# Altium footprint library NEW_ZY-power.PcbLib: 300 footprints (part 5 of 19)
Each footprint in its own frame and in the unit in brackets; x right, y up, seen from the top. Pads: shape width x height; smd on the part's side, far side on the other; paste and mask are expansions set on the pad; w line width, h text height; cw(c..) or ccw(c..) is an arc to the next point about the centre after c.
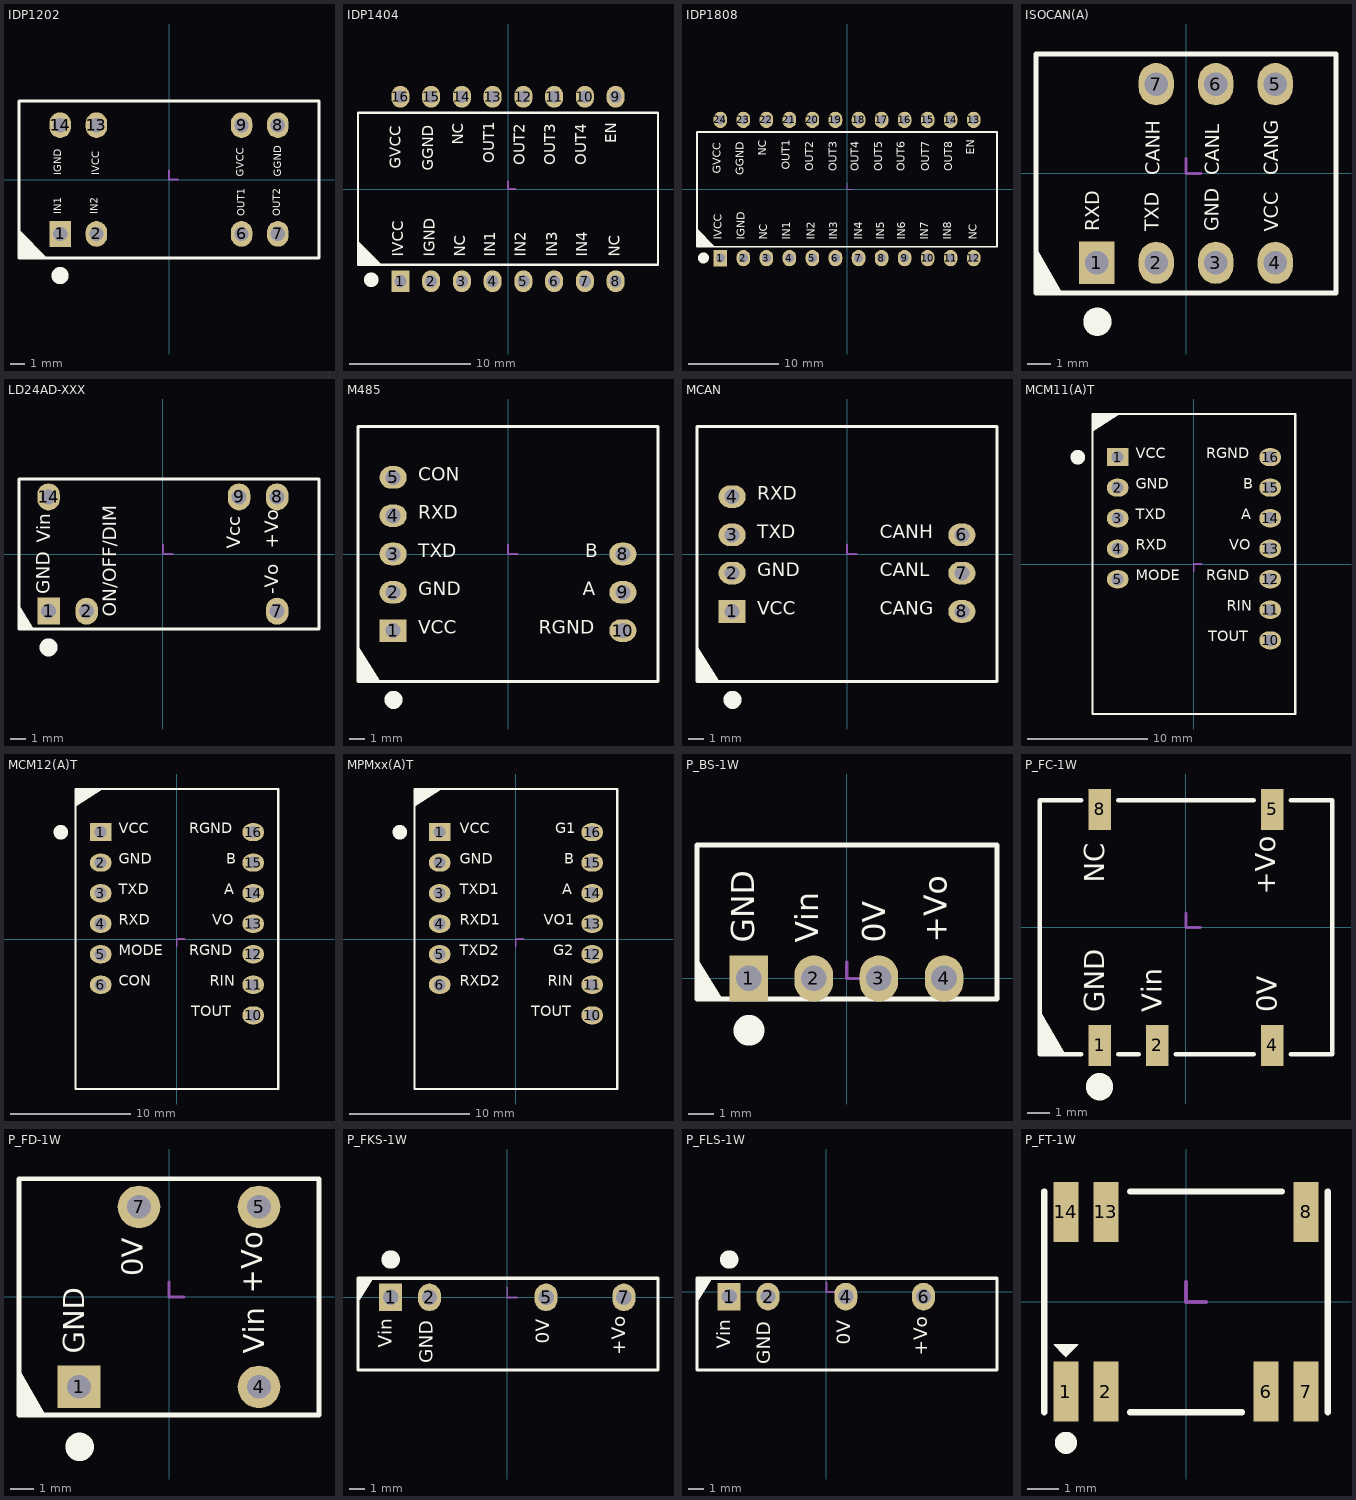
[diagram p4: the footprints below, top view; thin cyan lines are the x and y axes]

## IDP1202 [mm] "20x10x8mm"
height 8.001
pads (8):
  rect 1.5x1.8 hole 1: 1(-7.62,-3.81)
  oval 1.5x1.8 hole 1: 2(-5.08,-3.81) 6(5.08,-3.81) 7(7.62,-3.802) 8(7.62,3.81) 9(5.08,3.81) 13(-5.08,3.81) 14(-7.62,3.81)
Top Overlay:
  circle w1: c-7.62,-6.725 r0.1
  region: -10.5,-5.5 -8.525,-5.5 -10.5,-3.525
  lines w0.2: -10.5,-5.5 10.5,-5.5 10.5,5.5 -10.5,5.5 -10.5,-5.5
  text "IGND" at -7.366,0.305 h0.89
  text "IVCC" at -4.724,0.305 h0.89
  text "GVCC" at 5.41,0.178 h0.89
  text "GGND" at 8.026,0.178 h0.89
  text "OUT2" at 7.976,-2.565 h0.89
  text "OUT1" at 5.461,-2.565 h0.89
  text "IN1" at -7.366,-2.413 h0.89
  text "IN2" at -4.826,-2.413 h0.89
Mechanical 15:
  lines w0.127: 0,0.635 0,0 0.635,0

## IDP1404 [mm] "23.97x14.41x9.65mm"
height 9.652
pads (16):
  rect 1.5x1.8 hole 1: 1(-8.89,-7.62)
  oval 1.5x1.8 hole 1: 2(-6.35,-7.62) 3(-3.81,-7.62) 4(-1.27,-7.62) 5(1.27,-7.62) 6(3.81,-7.62) 7(6.35,-7.62) 8(8.89,-7.62) 9(8.89,7.62) 10(6.35,7.62) 11(3.81,7.62) 12(1.27,7.62) 13(-1.27,7.62) 14(-3.81,7.62) 15(-6.35,7.62) 16(-8.89,7.62)
Top Overlay:
  circle w1: c-11.303,-7.499 r0.1
  region: -12.39,-6.274 -10.415,-6.274 -12.39,-4.299
  lines w0.2: -12.39,-6.274 12.39,-6.274 12.39,6.299 -12.39,6.299 -12.39,-6.274
  text "IVCC" at -8.331,-5.588 h1.52
  text "IGND" at -5.74,-5.588 h1.52
  text "NC" at -3.2,-5.588 h1.52
  text "IN1" at -0.737,-5.588 h1.52
  text "IN2" at 1.778,-5.588 h1.52
  text "IN3" at 4.394,-5.588 h1.52
  text "IN4" at 6.883,-5.588 h1.52
  text "NC" at 9.576,-5.588 h1.52
  text "EN" at 9.271,3.791 h1.52
  text "OUT1" at -0.813,2.147 h1.52
  text "OUT2" at 1.702,1.968 h1.52
  text "OUT3" at 4.216,1.959 h1.52
  text "OUT4" at 6.782,1.962 h1.52
  text "NC" at -3.378,3.655 h1.52
  text "GGND" at -5.842,1.524 h1.52
  text "GVCC" at -8.509,1.655 h1.52
Mechanical 15:
  lines w0.127: 0,0.635 0,0 0.635,0

## IDP1808 [mm] "32.32x14.41x6.7(9.65)mm"
height 6.248
pads (24):
  rect 1.5x1.8 hole 1: 1(-13.97,-7.62)
  oval 1.5x1.8 hole 1: 2(-11.43,-7.62) 3(-8.89,-7.62) 4(-6.35,-7.62) 5(-3.81,-7.62) 6(-1.27,-7.62) 7(1.27,-7.62) 8(3.81,-7.62) 9(6.35,-7.62) 10(8.89,-7.62) 11(11.43,-7.62) 12(13.97,-7.62) 13(13.97,7.62) 14(11.43,7.62) 15(8.89,7.62) 16(6.35,7.62) 17(3.81,7.62) 18(1.27,7.62) 19(-1.27,7.62) 20(-3.81,7.62) 21(-6.35,7.62) 22(-8.89,7.62) 23(-11.43,7.62) 24(-13.97,7.62)
Top Overlay:
  circle w1: c-15.834,-7.6 r0.1
  region: -16.54,-6.375 -14.565,-6.375 -16.54,-4.401
  lines w0.2: -16.54,-6.375 -16.54,6.299 16.54,6.299 16.54,-6.375 -16.54,-6.375
  text "NC" at -8.56,3.655 h1.52
  text "GGND" at -11.049,1.524 h1.52
  text "GVCC" at -13.589,1.655 h1.52
  text "OUT8" at 11.913,1.956 h1.52
  text "OUT7" at 9.423,1.959 h1.52
  text "OUT6" at 6.706,1.959 h1.52
  text "OUT5" at 4.242,1.952 h1.52
  text "OUT4" at 1.651,1.962 h1.52
  text "OUT3" at -0.813,1.959 h1.52
  text "OUT2" at -3.404,1.968 h1.52
  text "OUT1" at -5.969,2.147 h1.52
  text "EN" at 14.376,3.791 h1.52
  text "NC" at 14.656,-5.588 h1.52
  text "IN8" at 11.811,-5.588 h1.52
  text "IN7" at 9.296,-5.588 h1.52
  text "IN6" at 6.756,-5.588 h1.52
  text "IN5" at 4.42,-5.588 h1.52
  text "IN4" at 2.007,-5.588 h1.52
  text "IN3" at -0.737,-5.588 h1.52
  text "IN2" at -3.251,-5.588 h1.52
  text "IN1" at -5.918,-5.588 h1.52
  text "NC" at -8.484,-5.588 h1.52
  text "IGND" at -10.947,-5.588 h1.52
  text "IVCC" at -13.487,-5.588 h1.52
Mechanical 15:
  lines w0.127: 0,0.635 0,0 0.635,0

## ISOCAN(A) [mm]
height 7.7
pads (7):
  rect 1.5x1.8 hole 1: 1(-3.81,-3.81)
  oval 1.5x1.8 hole 1: 2(-1.27,-3.81) 3(1.27,-3.81) 4(3.81,-3.81) 5(3.81,3.81) 6(1.27,3.81) 7(-1.27,3.81)
Top Overlay:
  circle w1: c-3.783,-6.325 r0.1
  region: -5.284,-5.1 -6.4,-3.161 -6.4,-5.1
  lines w0.2: -6.4,-5.1 -6.4,5.1 6.4,5.1 6.4,-5.1 -6.4,-5.1
  text "CANG" at 4.14,-0.072 h1.02
  text "CANL" at 1.64,-0.072 h1.02
  text "CANH" at -0.914,-0.072 h1.02
  text "VCC" at 4.14,-2.485 h1.02
  text "GND" at 1.6,-2.459 h1.02
  text "TXD" at -0.94,-2.459 h1.02
  text "RXD" at -3.491,-2.459 h1.02
Mechanical 15:
  lines w0.127: 0,0.635 0,0 0.635,0

## LD24AD-XXX [mm]
pads (6):
  rect 1.5x1.8 hole 1: 1(-7.62,-3.81)
  oval 1.5x1.8 hole 1: 2(-5.08,-3.81) 7(7.62,-3.81) 8(7.62,3.81) 9(5.08,3.81) 14(-7.62,3.81)
Top Overlay:
  circle w1: c-7.62,-6.225 r0.1
  region: -9.59,-3.414 -9.59,-5 -8.596,-5
  lines w0.2: -9.59,-5 -9.59,5 10.41,5 10.41,-5 -9.59,-5
  text "-Vo" at 8.001,-2.667 h1.52
  text "+Vo" at 8.001,0.338 h1.52
  text "Vcc" at 5.461,0.339 h1.52
  text "GND" at -7.239,-2.667 h1.52
  text "Vin" at -7.223,0.762 h1.52
  text "ON/OFF/DIM" at -2.794,-4.191 h1.52
Mechanical 15:
  lines w0.127: 0,0.635 0,0 0.635,0

## M485 [mm]
height 7.1
pads (8):
  rect 1.8x1.5 hole 1: 1(-7.62,-5.08)
  oval 1.8x1.5 hole 1: 2(-7.62,-2.54) 3(-7.62,0) 4(-7.62,2.54) 5(-7.62,5.08) 8(7.62,0) 9(7.62,-2.54) 10(7.62,-5.08)
Top Overlay:
  circle w1: c-7.593,-9.675 r0.1
  region: -9.95,-6.12 -9.95,-8.45 -8.49,-8.45
  lines w0.2: -9.95,-8.45 9.95,-8.45 9.95,8.45 -9.95,8.45 -9.95,-8.45
  text "GND" at -5.939,-3.048 h1.52
  text "VCC" at -5.938,-5.588 h1.52
  text "TXD" at -5.939,-0.508 h1.52
  text "RXD" at -5.939,2.032 h1.52
  text "CON" at -5.939,4.572 h1.52
  text "B" at 5.126,-0.508 h1.52
  text "A" at 4.952,-3.048 h1.52
  text "RGND" at 2.032,-5.588 h1.52
Mechanical 15:
  lines w0.127: 0,0.635 0,0 0.635,0

## MCAN [mm]
height 7.1
pads (7):
  rect 1.8x1.5 hole 1: 1(-7.62,-3.81)
  oval 1.8x1.5 hole 1: 2(-7.62,-1.27) 3(-7.62,1.27) 4(-7.62,3.81) 6(7.62,1.27) 7(7.62,-1.27) 8(7.62,-3.81)
Top Overlay:
  circle w1: c-7.593,-9.675 r0.1
  region: -9.95,-6.12 -9.95,-8.45 -8.49,-8.45
  lines w0.2: -9.95,-8.45 9.95,-8.45 9.95,8.45 -9.95,8.45 -9.95,-8.45
  text "CANG" at 2.189,-4.318 h1.52
  text "CANL" at 2.189,-1.778 h1.52
  text "CANH" at 2.189,0.762 h1.52
  text "GND" at -5.939,-1.778 h1.52
  text "TXD" at -5.939,0.762 h1.52
  text "RXD" at -5.939,3.302 h1.52
  text "VCC" at -5.938,-4.318 h1.52
Mechanical 15:
  lines w0.127: 0,0.635 0,0 0.635,0

## MCM11(A)T [mm]
height 7.1
pads (12):
  rect 1.8x1.5 hole 1: 1(-6.35,8.89)
  oval 1.8x1.5 hole 1: 2(-6.35,6.35) 3(-6.35,3.81) 4(-6.35,1.27) 5(-6.35,-1.27) 10(6.35,-6.35) 11(6.35,-3.81) 12(6.35,-1.27) 13(6.35,1.27) 14(6.35,3.81) 15(6.35,6.35) 16(6.35,8.89)
Top Overlay:
  circle w1: c-9.675,8.89 r0.1
  region: -6.12,12.49 -8.45,12.49 -8.45,11.03
  lines w0.2: -8.45,-12.49 -8.45,12.49 8.45,12.49 8.45,-12.49 -8.45,-12.49
  text "MODE" at -4.827,-1.651 h1.52
  text "RGND" at 1.016,8.509 h1.52
  text "B" at 4.11,5.969 h1.52
  text "A" at 3.936,3.429 h1.52
  text "VO" at 2.945,0.889 h1.52
  text "RGND" at 1.016,-1.651 h1.52
  text "RIN" at 2.719,-4.191 h1.52
  text "TOUT" at 1.2,-6.731 h1.52
  text "RXD" at -4.827,0.889 h1.52
  text "TXD" at -4.827,3.429 h1.52
  text "GND" at -4.827,5.969 h1.52
  text "VCC" at -4.826,8.509 h1.52
Mechanical 15:
  lines w0.127: 0,-0.635 0,0 0.635,0

## MCM12(A)T [mm]
height 7.1
pads (13):
  rect 1.8x1.5 hole 1: 1(-6.35,8.89)
  oval 1.8x1.5 hole 1: 2(-6.35,6.35) 3(-6.35,3.81) 4(-6.35,1.27) 5(-6.35,-1.27) 6(-6.35,-3.81) 10(6.35,-6.35) 11(6.35,-3.81) 12(6.35,-1.27) 13(6.35,1.27) 14(6.35,3.81) 15(6.35,6.35) 16(6.35,8.89)
Top Overlay:
  circle w1: c-9.675,8.89 r0.1
  region: -6.12,12.49 -8.45,12.49 -8.45,11.03
  lines w0.2: -8.45,-12.49 8.45,-12.49 8.45,12.49 -8.45,12.49 -8.45,-12.49
  text "VCC" at -4.826,8.509 h1.52
  text "GND" at -4.827,5.969 h1.52
  text "TXD" at -4.827,3.429 h1.52
  text "RXD" at -4.827,0.889 h1.52
  text "TOUT" at 1.2,-6.731 h1.52
  text "RIN" at 2.719,-4.191 h1.52
  text "RGND" at 1.016,-1.651 h1.52
  text "VO" at 2.945,0.889 h1.52
  text "A" at 3.936,3.429 h1.52
  text "B" at 4.11,5.969 h1.52
  text "RGND" at 1.016,8.509 h1.52
  text "CON" at -4.827,-4.191 h1.52
  text "MODE" at -4.827,-1.651 h1.52
Mechanical 15:
  lines w0.127: 0,-0.635 0,0 0.635,0

## MPMxx(A)T [mm]
height 7.1
pads (13):
  rect 1.8x1.5 hole 1: 1(-6.35,8.89)
  oval 1.8x1.5 hole 1: 2(-6.35,6.35) 3(-6.35,3.81) 4(-6.35,1.27) 5(-6.35,-1.27) 6(-6.35,-3.81) 10(6.35,-6.35) 11(6.35,-3.81) 12(6.35,-1.27) 13(6.35,1.27) 14(6.35,3.81) 15(6.35,6.35) 16(6.35,8.89)
Top Overlay:
  circle w1: c-9.675,8.89 r0.1
  region: -6.12,12.49 -8.45,12.49 -8.45,11.03
  lines w0.2: -8.45,-12.49 8.45,-12.49 8.45,12.49 -8.45,12.49 -8.45,-12.49
  text "VCC" at -4.699,8.509 h1.52
  text "GND" at -4.7,5.969 h1.52
  text "TXD1" at -4.7,3.429 h1.52
  text "RXD1" at -4.7,0.889 h1.52
  text "TOUT" at 1.255,-6.731 h1.52
  text "RIN" at 2.647,-4.191 h1.52
  text "G2" at 3.101,-1.651 h1.52
  text "VO1" at 2.303,0.889 h1.52
  text "A" at 3.864,3.429 h1.52
  text "B" at 4.037,5.969 h1.52
  text "G1" at 3.28,8.509 h1.52
  text "RXD2" at -4.7,-4.191 h1.52
  text "TXD2" at -4.7,-1.651 h1.52
Mechanical 15:
  lines w0.127: 0,-0.635 0,0 0.635,0

## P_BS-1W [mm]
height 10.1
pads (4):
  rect 1.5x1.8 hole 1: 1(-3.823,0)
  oval 1.5x1.8 hole 1: 2(-1.283,0) 3(1.257,0) 4(3.797,0)
Top Overlay:
  circle w1: c-3.81,-2.025 r0.1
  region: -5.837,0.786 -5.837,-0.8 -4.844,-0.8
  lines w0.2: -5.837,-0.8 -5.837,5.2 5.863,5.2 5.863,-0.8 -5.837,-0.8
  text "+Vo" at 4.204,1.396 h1.52
  text "0V" at 1.791,1.396 h1.52
  text "Vin" at -0.826,1.397 h1.52
  text "GND" at -3.315,1.396 h1.52
Mechanical 15:
  lines w0.127: 0,0.635 0,0 0.635,0

## P_FC-1W [mm]
height 7.14
pads (5):
  rect 1x1.8 smd: 1(-3.81,-5.203) 2(-1.27,-5.203) 4(3.81,-5.203) 5(3.81,5.203) 8(-3.81,5.203)
Top Overlay:
  circle w1: c-3.812,-7.026 r0.1
  region: -5.334,-5.6 -6.45,-3.661 -6.45,-5.6
  lines w0.2: -4.623,-5.6 -6.45,-5.6 -6.45,5.6 -4.623,5.6 ; -2.997,-5.6 -2.084,-5.6 ; -2.997,5.6 2.997,5.6 ; -0.456,-5.6 2.997,-5.6 ; 4.623,-5.6 6.45,-5.6 6.45,5.6 4.623,5.6
  text "NC" at -3.302,1.972 h1.52
  text "Vin" at -0.762,-3.739 h1.52
  text "+Vo" at 4.244,1.443 h1.52
  text "0V" at 4.318,-3.741 h1.52
  text "GND" at -3.302,-3.741 h1.52
Mechanical 15:
  lines w0.127: 0,0.635 0,0 0.635,0

## P_FD-1W [mm]
height 7.7
pads (4):
  rect 1.8x1.8 hole 1: 1(-3.81,-3.81)
  round 1.8 hole 1: 4(3.81,-3.81) 5(3.81,3.81) 7(-1.27,3.81)
Top Overlay:
  circle w1: c-3.783,-6.35 r0.1
  region: -5.234,-5 -6.35,-3.061 -6.35,-5
  lines w0.2: -6.35,-5 -6.35,5 6.35,5 6.35,-5 -6.35,-5
  text "0V" at -0.813,0.864 h1.52
  text "+Vo" at 4.244,0.127 h1.52
  text "Vin" at 4.318,-2.413 h1.52
  text "GND" at -3.302,-2.413 h1.52
Mechanical 15:
  lines w0.127: 0,0.635 0,0 0.635,0

## P_FKS-1W [mm]
height 10.1
pads (4):
  rect 1.5x1.8 hole 1: 1(-7.62,0)
  oval 1.5x1.8 hole 1: 2(-5.08,0) 5(2.54,0) 7(7.62,0)
Top Overlay:
  circle w1: c-7.62,2.475 r0.1
  region: -9.75,-0.336 -9.75,1.25 -8.756,1.25
  lines w0.2: -9.75,-4.75 -9.75,1.25 9.85,1.25 9.85,-4.75 -9.75,-4.75
  text "+Vo" at 8.001,-3.776 h1.52
  text "0V" at 3.048,-3.036 h1.52
  text "GND" at -4.572,-4.318 h1.52
  text "Vin" at -7.239,-3.308 h1.52
Mechanical 15:
  lines w0.127: 0,0.635 0,0 0.635,0

## P_FLS-1W [mm]
height 10.1
pads (4):
  rect 1.5x1.8 hole 1: 1(-6.35,-0.3)
  oval 1.5x1.8 hole 1: 2(-3.81,-0.3) 4(1.27,-0.3) 6(6.35,-0.3)
Top Overlay:
  circle w1: c-6.35,2.125 r0.1
  region: -8.45,-0.686 -8.45,0.9 -7.456,0.9
  lines w0.2: -8.45,-5.1 11.15,-5.1 11.15,0.9 -8.45,0.9 -8.45,-5.1
  text "Vin" at -5.969,-3.704 h1.52
  text "GND" at -3.378,-4.714 h1.52
  text "0V" at 1.854,-3.432 h1.52
  text "+Vo" at 6.883,-4.172 h1.52
Mechanical 15:
  lines w0.127: 0,0.635 0,0 0.635,0

## P_FT-1W [mm]
height 3
pads (7):
  rect 0.8x1.9 smd: 1(-3.81,-2.85) 2(-2.54,-2.85) 6(2.54,-2.85) 7(3.81,-2.85) 8(3.81,2.85) 13(-2.54,2.85) 14(-3.81,2.85)
Top Overlay:
  circle w0.5: c-3.81,-4.474 r0.1
  region: -4.187,-1.358 -3.81,-1.734 -3.433,-1.358
  lines w0.051: -4.187,-1.358 -3.861,-1.684 -3.81,-1.734 -3.759,-1.684 -3.433,-1.358 -4.187,-1.358
  lines w0.2: -4.5,-3.5 -4.5,3.5 ; -1.778,-3.5 1.778,-3.5 ; -1.778,3.5 3.048,3.5 ; 4.5,-3.5 4.5,3.5
Mechanical 15:
  lines w0.127: 0,0.635 0,0 0.635,0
